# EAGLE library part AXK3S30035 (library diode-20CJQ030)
Matsushita P6 NARROW-PITCH CONNECTORS FOR PC BOARDS 30Pin Socket NARROW-PITCH (0.6mm) CONNECTORS P6 SERIES FEATURES The product lineup consists of the low profile of: - 4 mm - 5 mm - 6 mm - 7 mm - 8 mm - 9 mm APPLICATIONS Small portable equipment, laptop computers, video equipment, radio communication, cellular telephones, etc. Please send any comments to: messi@users.sourceforge.net
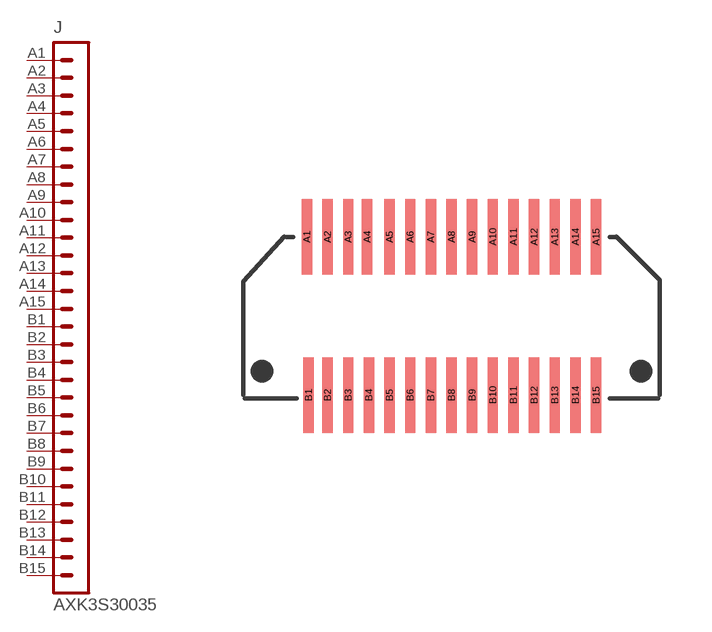
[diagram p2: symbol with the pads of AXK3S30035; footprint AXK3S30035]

Designator prefix J

## AXK3S30035  [AXK3S30035]
A1  1  pas
A2  2  pas
A3  3  pas
A4  4  pas
A5  5  pas
A6  6  pas
A7  7  pas
A8  8  pas
A9  9  pas
A10  10  pas
A11  11  pas
A12  12  pas
A13  13  pas
A14  14  pas
A15  15  pas
B1  16  pas
B2  17  pas
B3  18  pas
B4  19  pas
B5  20  pas
B6  21  pas
B7  22  pas
B8  23  pas
B9  24  pas
B10  25  pas
B11  26  pas
B12  27  pas
B13  28  pas
B14  29  pas
B15  30  pas

## Footprint AXK3S30035 (pad centres in mm)
Matsushita NARROW-PITCH CONNECTORS FOR PC BOARDS 30Pin Socket NARROW-PITCH (0.6mm) CONNECTORS P6 SERIES FEATURES The product lineup consists of the low profile of: - 4 mm - 5 mm - 6 mm - 7 mm - 8 mm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
smd 0.3 x 2.2: A1 -4.2,2.3; A2 -3.6,2.3; A3 -3,2.3; A4 -2.45,2.3; A5 -1.8,2.3; A6 -1.2,2.3; A7 -0.6,2.3; A8 0,2.3; A9 0.6,2.3; A10 1.2,2.3; A11 1.8,2.3; A12 2.4,2.3; A13 3,2.3; A14 3.6,2.3; A15 4.2,2.3; B1 -4.15,-2.3; B2 -3.6,-2.3; B3 -3,-2.3; B4 -2.4,-2.3; B5 -1.8,-2.3; B6 -1.2,-2.3; B7 -0.6,-2.3; B8 0,-2.3; B9 0.6,-2.3; B10 1.2,-2.3; B11 1.8,-2.3; B12 2.4,-2.3; B13 3,-2.3; B14 3.6,-2.3; B15 4.2,-2.3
